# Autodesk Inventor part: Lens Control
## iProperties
Created: 2006-10
Part Number: Lens Control
Document SubType Name: Modeling
Designer: Lab User
Author: Lab User
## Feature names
1. Extrusion1
2. Extrusion3
3. Hole2
